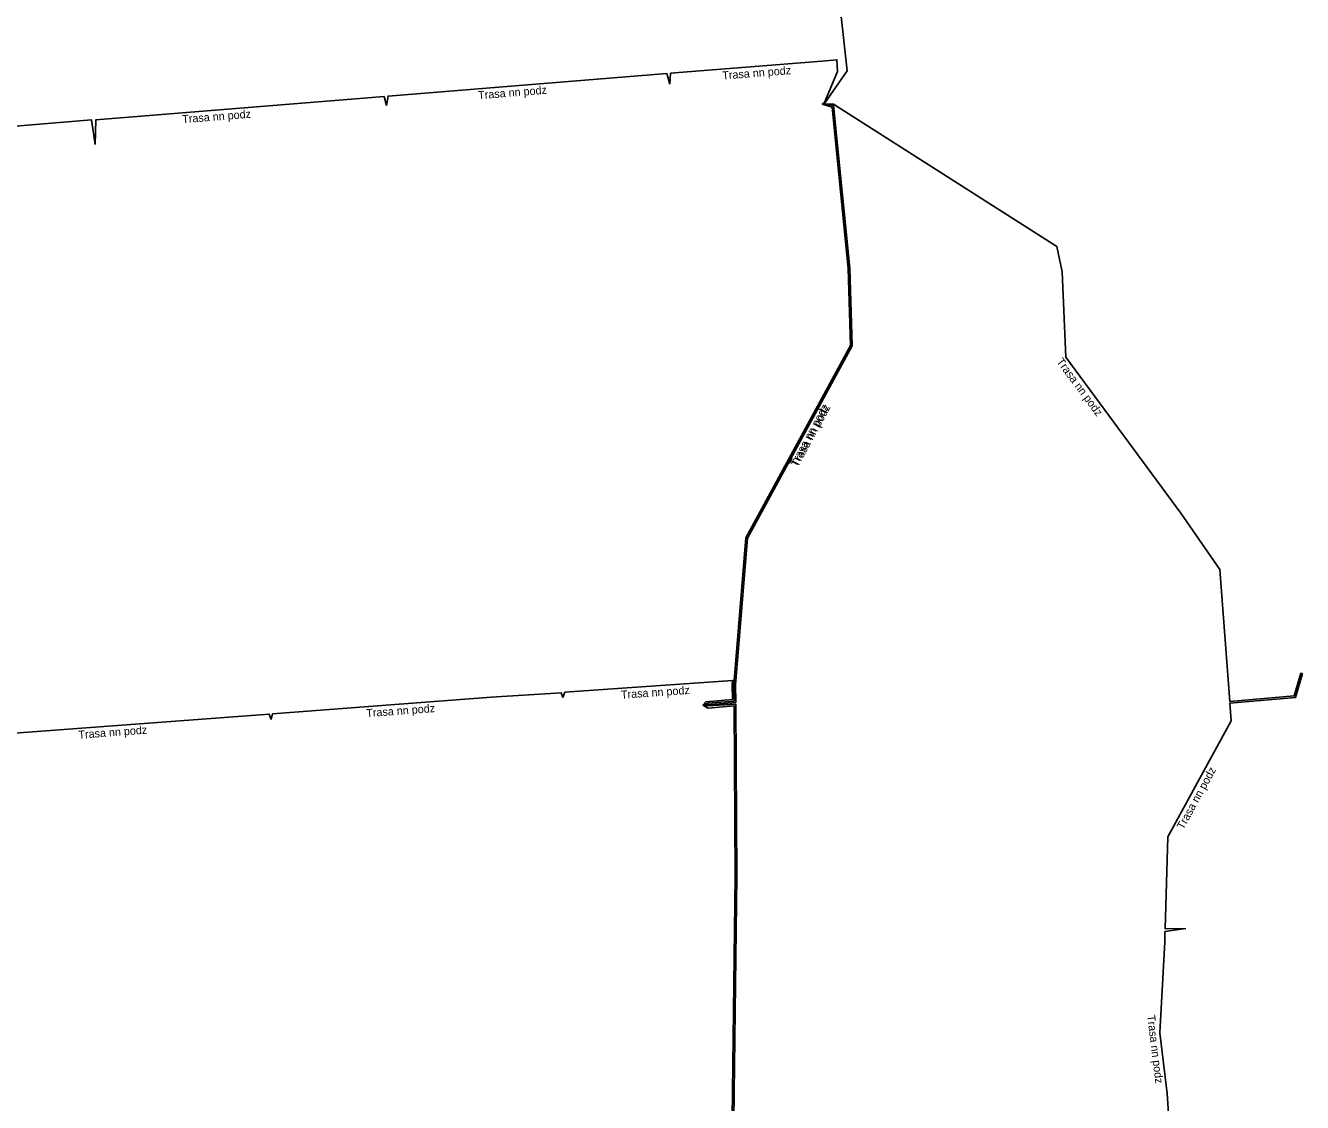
# Model space of a CAD drawing. Extents: x -873583 to -872966, y -1012951 to -1012536.
# Drawn here: x -873138.5 to -873059.4, y -1012682.3 to -1012615.5 of the extents above; entities that cross this region are included whole.
import ezdxf

# ---------------------------------------------------------------- set-up
doc = ezdxf.new("R2010")
doc.units = 0
doc.layers.add('Popiskový text - Ostatní atributy Trasy', color=7, linetype='Continuous')
doc.layers.add('Spojnice NN', color=7, linetype='Continuous')

msp = doc.modelspace()

# ---------------------------------------------------------------- linework, layer by layer
at = {"layer": 'Spojnice NN'}
for points in [[(-873089.141, -1012620.372), (-873088.968, -1012620.253), (-873087.6, -1012618.291), (-873088.294, -1012611.912), (-873086.516, -1012607.283), (-873087.024, -1012594.755), (-873086.821, -1012593.336), (-873085.01, -1012589.089), (-873086.145, -1012576.816), (-873086.38, -1012574.925), (-873086.876, -1012572.352), (-873088.726, -1012566.376), (-873095.781, -1012560.587), (-873106.167, -1012554.789), (-873106.778, -1012544.109), (-873106.806, -1012536.188), (-873109.173, -1012536.378), (-873109.501, -1012536.366)], [(-873098.584, -1012619.123), (-873098.544, -1012618.444), (-873089.173, -1012617.7), (-873088.234, -1012617.611), (-873088.198, -1012618.33), (-873089, -1012620.272), (-873089.141, -1012620.372)], [(-873116.159, -1012620.445), (-873116.058, -1012619.861), (-873098.783, -1012618.469), (-873098.584, -1012619.123)], [(-873134.231, -1012622.861), (-873134.181, -1012621.33), (-873116.311, -1012619.891), (-873116.159, -1012620.445)], [(-873096.543, -1012657.653), (-873096.233, -1012657.527), (-873094.61, -1012657.391), (-873094.619, -1012656.373), (-873093.87, -1012647.265), (-873087.385, -1012635.335), (-873087.532, -1012630.55), (-873088.53, -1012620.56), (-873089.141, -1012620.372)], [(-873096.543, -1012657.653), (-873096.248, -1012657.628), (-873094.51, -1012657.483), (-873094.519, -1012656.377), (-873093.773, -1012647.295), (-873087.284, -1012635.359), (-873087.433, -1012630.545), (-873088.44, -1012620.458), (-873089.141, -1012620.372)], [(-873089.141, -1012620.372), (-873088.442, -1012620.358), (-873074.602, -1012629.187), (-873074.273, -1012630.766), (-873074.041, -1012636.064), (-873066.901, -1012645.727), (-873064.492, -1012649.233), (-873063.876, -1012657.417), (-873059.871, -1012657.072), (-873059.457, -1012655.667), (-873059.366, -1012655.687)], [(-873151.875, -1012623.274), (-873151.769, -1012622.683), (-873142.877, -1012622.032), (-873134.444, -1012621.345), (-873134.231, -1012622.861)], [(-873096.543, -1012657.653), (-873096.361, -1012657.437), (-873094.711, -1012657.3), (-873094.719, -1012656.369), (-873094.697, -1012656.107), (-873105.102, -1012656.845), (-873105.236, -1012657.168)], [(-873059.366, -1012655.687), (-873059.794, -1012657.166), (-873063.868, -1012657.516), (-873063.785, -1012658.613), (-873067.714, -1012665.805), (-873067.885, -1012671.516), (-873066.607, -1012671.488)], [(-873105.236, -1012657.168), (-873105.325, -1012656.871), (-873109.665, -1012657.159), (-873123.228, -1012658.179), (-873123.314, -1012658.538)], [(-873130.472, -1012725.94), (-873130.159, -1012726.063), (-873128.997, -1012725.666), (-873130.141, -1012718.456), (-873122.81, -1012712.344), (-873109.109, -1012701.646), (-873109.288, -1012690.336), (-873109.203, -1012687.296), (-873094.672, -1012686.744), (-873094.438, -1012668.249), (-873094.501, -1012657.584), (-873096.261, -1012657.678), (-873096.543, -1012657.653)], [(-873096.543, -1012657.653), (-873096.22, -1012657.827), (-873094.6, -1012657.692), (-873094.538, -1012668.249), (-873094.771, -1012686.648), (-873109.207, -1012687.196), (-873112.537, -1012687.362), (-873118.302, -1012687.798), (-873118.092, -1012691.007)], [(-873123.314, -1012658.538), (-873123.438, -1012658.194), (-873140.893, -1012659.505), (-873140.986, -1012659.836)], [(-873066.607, -1012671.488), (-873067.89, -1012671.693), (-873067.909, -1012672.327), (-873068.215, -1012677.962), (-873067.749, -1012681.739), (-873067.486, -1012685.785), (-873067.766, -1012688.418), (-873066.733, -1012688.611)]]:
    msp.add_lwpolyline(points, dxfattribs=at)

# ---------------------------------------------------------------- texts
at = {"layer": 'Popiskový text - Ostatní atributy Trasy'}
for rotation, p in [(4.54421, (-873095.321, -1012618.841)), (4.60872, (-873110.46, -1012620.062)), (4.6038, (-873128.808, -1012621.55)), (306.46407, (-873074.645, -1012636.341)), (61.47255, (-873090.762, -1012642.906)), (61.46981, (-873090.649, -1012642.91)), (4.05685, (-873101.605, -1012657.248)), (4.30194, (-873117.397, -1012658.392)), (4.29452, (-873135.245, -1012659.732)), (61.35216, (-873066.752, -1012665.399)), (277.03397, (-873069.002, -1012676.894))]:
    msp.add_text('Trasa nn podz', height=0.5, rotation=rotation, dxfattribs=at).set_placement(p)

doc.saveas('drawing.dxf')
